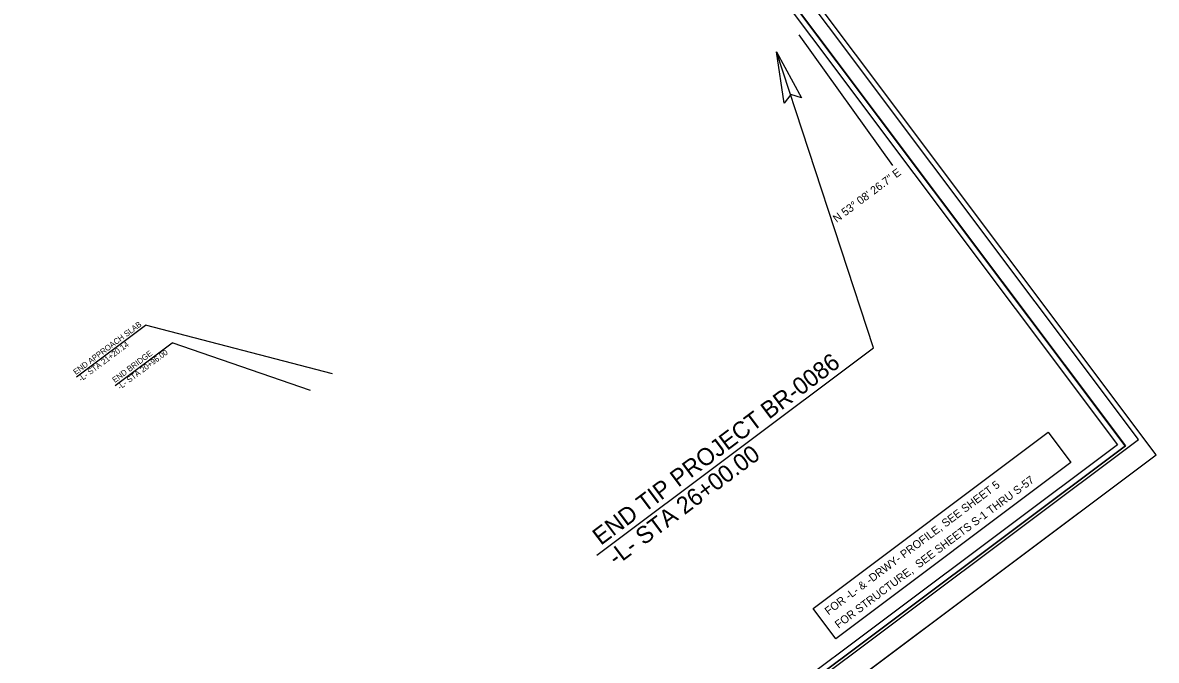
# Model space of a CAD drawing. Extents: x 2186558 to 2188589, y 629855 to 631741.
# Drawn here: x 2187597 to 2188589, y 630685 to 631243 of the extents above; entities that cross this region are included whole.
import ezdxf

# ---------------------------------------------------------------- set-up
doc = ezdxf.new("R2010")
doc.units = 0
for name, color, linetype in [('Prop Dimension', 7, 'Continuous'), ('Prop Dimension Text', 7, 'Continuous'), ('Prop Grid Mask', 7, 'Continuous'), ('Prop Horizontal Alignment Direction Label', 7, 'Continuous'), ('Prop Terminator CELL', 7, 'Continuous'), ('Prop VPI Label', 7, 'Continuous'), ('Scratch_Level_8', 7, 'Continuous'), ('Sheet Cutting Line CELL', 7, 'Continuous'), ('Sheet Plan CELL', 7, 'Continuous'), ('Sheet Plan Layout CELL', 7, 'Continuous'), ('Sheet Plot Border Inside CELL', 7, 'Continuous'), ('Sheet Plot Border Outside CELL', 7, 'Continuous')]:
    doc.layers.add(name, color=color, linetype=linetype)

msp = doc.modelspace()

# ---------------------------------------------------------------- linework, layer by layer
at = {"layer": 'Prop Dimension'}
for p, q in [((2188341.52, 630958.56), (2188256.45, 631217.81)), ((2187644.2, 630933.14), (2187704.53, 630978.41)), ((2187868.23, 630935.79), (2187704.53, 630978.41)), ((2187678.01, 630925.66), (2187727.81, 630963.03)), ((2187848.91, 630921.31), (2187727.81, 630963.03)), ((2188099.28, 630776.95), (2188341.52, 630958.56))]:
    msp.add_line(p, q, dxfattribs=at)
at = {"layer": 'Prop Grid Mask'}
msp.add_lwpolyline([(2188288.52, 630730.34), (2188494.25, 630884.71), (2188514.14, 630858.2), (2188308.41, 630703.83)], close=True, dxfattribs=at)
at = {"layer": 'Prop Horizontal Alignment Direction Label'}
msp.add_line((2188276.25, 631232.66), (2188358.19, 631118.05), dxfattribs=at)
at = {"layer": 'Prop Terminator CELL'}
msp.add_lwpolyline([(2188263.4, 631172.68), (2188256.45, 631217.81), (2188278.42, 631177.45), (2188269, 631180.36)], close=True, dxfattribs=at)
at = {"layer": 'Scratch_Level_8'}
msp.add_lwpolyline([(2186738.7, 630811.99), (2187930.9, 631705.79), (2188554.73, 630873.69), (2187362.53, 629979.89)], close=True, dxfattribs=at)
at = {"layer": 'Sheet Cutting Line CELL'}
msp.add_line((2187241.85, 629855.03), (2188588.83, 630864.88), dxfattribs=at)
at = {"layer": 'Sheet Plan CELL'}
for points in [[(2187931.9, 631712.82), (2186731.71, 630813.02), (2187361.55, 629972.91), (2188561.73, 630872.69)], [(2187361.55, 629972.91), (2186731.7, 630812.99), (2187771.81, 631592.82), (2187861.84, 631472.76), (2188021.9, 631592.74), (2188561.73, 630872.69)]]:
    msp.add_lwpolyline(points, close=True, dxfattribs=at)
at = {"layer": 'Sheet Plan Layout CELL'}
msp.add_lwpolyline([(2186731.7, 630812.99), (2187361.55, 629972.91), (2188561.72, 630872.68), (2188058.73, 631543.59), (2187867.31, 631400.07), (2187740.45, 631569.29)], close=True, dxfattribs=at)
at = {"layer": 'Sheet Plot Border Inside CELL'}
msp.add_lwpolyline([(2187240.25, 629878.83), (2188573.22, 630878.18), (2187940.39, 631722.3), (2186607.41, 630722.95)], close=True, dxfattribs=at)
at = {"layer": 'Sheet Plot Border Outside CELL'}
msp.add_lwpolyline([(2187241.85, 629855.03), (2188588.83, 630864.88), (2187932, 631741), (2186585.01, 630731.15)], close=True, dxfattribs=at)

# ---------------------------------------------------------------- texts
at = {"layer": 'Prop Dimension Text'}
for s, height, p in [('END APPROACH SLAB', 5, (2187643.73, 630934.67)), ('-L- STA 21+20.14', 5, (2187648.23, 630928.67)), ('END BRIDGE', 5, (2187677.86, 630927.7)), ('-L- STA 20+96.00', 5, (2187682.36, 630921.7)), ('END TIP PROJECT BR-0086', 15, (2188102.87, 630785.17)), ('-L- STA 26+00.00', 15, (2188116.36, 630767.17))]:
    msp.add_text(s, height=height, rotation=36.85926, dxfattribs=at).set_placement(p)
at = {"layer": 'Prop Horizontal Alignment Direction Label'}
msp.add_text('N 53%%d 08\' 26.7" E', height=7, rotation=36.85925, dxfattribs=at).set_placement((2188309.18, 631067.86))
at = {"layer": 'Prop VPI Label'}
for s, p in [('FOR -L- & -DRWY- PROFILE, SEE SHEET 5', (2188302.03, 630724.29)), ('FOR STRUCTURE,  SEE SHEETS S-1 THRU S-57', (2188310.85, 630712.54))]:
    msp.add_text(s, height=7, rotation=36.88292, dxfattribs=at).set_placement(p)

doc.saveas('drawing.dxf')
